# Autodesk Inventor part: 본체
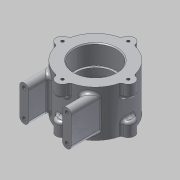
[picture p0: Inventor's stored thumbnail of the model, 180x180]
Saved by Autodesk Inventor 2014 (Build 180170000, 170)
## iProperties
Created: 2015-03
Part Number: 본체
Material: 알루미늄 6061
Document SubType Name: Modeling
Designer: MYHOME
Mass: 450.776 g
Surface Area: 332.745 cm^2
Volume: 166.338 cm^3
Density: 2.71 g/cm^3
Appearance: 알루미늄 - 평지
Author: MYHOME
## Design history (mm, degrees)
sketch "스케치1"
  geometry: C1 r 37 at (0, 0); 1 further point
  constraints: 1 centre point, 1 coincident
  dimensions: "d0" = 74 diameter of C1
extrude "돌출1" new body sketch "스케치1" distance "d1" = 52; taper "d2" = 0 deg
sketch "스케치2"
  geometry: C1 r 7 at (0, 37); C2 r 7 at (-37, 0); C3 r 7 at (0, -37); C4 r 7 at (37, 0); A1 r 37 centre (0, 0) between (0, 37) and (-37, 0) reference
  constraints: 4 centre point, 4 point on circle, 2 horizontal alignment, 2 vertical alignment
  dimensions: "d3" = 14 diameter of C1; "d4" = 14 diameter of C2; "d5" = 14 diameter of C3; "d6" = 14 diameter of C4
extrude "돌출2" join sketch "스케치2" distance "d7" = 15; taper "d8" = 0 deg
sketch "스케치3"
  geometry: A1 r 7 centre (0, 37) between (6.969, 36.338) and (-6.969, 36.338) reference; A2 r 7 centre (-37, 0) between (-36.338, 6.969) and (-36.338, -6.969) reference; A3 r 7 centre (0, -37) between (-6.969, -36.338) and (6.969, -36.338) reference; A4 r 7 centre (37, 0) between (36.338, -6.969) and (36.338, 6.969) reference; 4 further points
  constraints: 4 coincident
hole "구멍1" sketch "스케치3" at (-37, 0), (0, -37), (37, 0), (0, 37) diameter "d9" = 3.242; stored, may be unused: countersink angle "d13" = 90 deg, drill point angle "d15" = 118 deg; dims "d10" = 8, "d11" = 4, "d12" = 2, "d14" = 11
node "작업 평면1"
hole "구멍2" diameter "d19" = 47; stored, may be unused: countersink angle "d23" = 90 deg, drill point angle "d25" = 0 deg; dims "d17" = 10, "d18" = 10, "d20" = 8, "d21" = 4, "d22" = 2, "d24" = 22
hole "구멍3" diameter "d28" = 42; stored, may be unused: countersink angle "d32" = 90 deg, drill point angle "d34" = 0 deg; dims "d26" = 10, "d27" = 10, "d29" = 8, "d30" = 47, "d31" = 22, "d33" = 30
sketch "스케치4"
  geometry: L1 (29, -22.978)-(29, -56); L2 (29, -56)-(19, -56); L3 (19, -56)-(19, -31.749); A1 r 37 centre (0, 0) between (-36.338, -6.969) and (-6.969, -36.338) reference; A2 r 37 centre (0, 0) between (6.969, -36.338) and (36.338, -6.969) reference; 1 further point
  constraints: 6 end point, 2 point on circle, 1 parallel, 1 perpendicular, 1 vertical
  dimensions: "d35" = 10 distance of L1.end L2.end; "d36" = 56 vertical distance of point (0, 0) L1.end; "d37" = 29 horizontal distance of L1.end point (0, 0)
extrude "돌출3" join sketch "스케치4" stored distance "d38" = 40; taper "d39" = 0 deg
fillet "모깎기1" dims "d40" = 5
chamfer "모따기1" distance "d41" = 1; stored, may be unused: second distance "d42" = 2, angle "d43" = 45 deg
fillet "모깎기2" dims "d44" = 0.3
sketch "스케치5"
  geometry: L1 (-43, 0)-(-43, 30) reference; L2 (-53, 0)-(-53, 30) reference; A1 r 5 centre (0, 0) between (-5, 0) and (5, 0) reference; A2 r 5 centre (0, 30) between (5, 30) and (-5, 30) reference; A3 r 5 centre (-48, 0) between (-53, 0) and (-43, 0) reference; A4 r 5 centre (-48, 30) between (-43, 30) and (-53, 30) reference; 5 further points
  constraints: 4 coincident
hole "구멍4" sketch "스케치5" at (-48, 30), (-48, 0), (0, 0), (0, 30) diameter "d45" = 4.134; stored, may be unused: countersink angle "d49" = 90 deg, drill point angle "d51" = 118 deg; dims "d46" = 6, "d47" = 47, "d48" = 22, "d50" = 8
sketch "스케치6"
  geometry: L1 (0, 0)-(-37, 0); L2 (0, 0)-(-26.163, 26.163); A1 r 37 centre (0, 0) between (-6.969, 36.338) and (-36.338, 6.969) reference; A2 r 7 centre (-37, 0) between (-36.338, 6.969) and (-36.338, -6.969) reference; 1 further point
  constraints: 4 end point, 1 horizontal, 1 point on circle
node "작업 평면2"
sketch "스케치7"
  geometry: L1 (-20.767, -26)-(20.767, -26) reference; 3 further points
  constraints: 1 coincident, 1 other
  dimensions: "d58" = 26 distance from line of L1 point (0, 0)
feature "엠보싱1" sketch "스케치7" dims "d52" = 0.5, "d53" = 0
fillet "모깎기3" dims "d54" = 3
fillet "모깎기4" dims "d55" = 3
fillet "모깎기5" dims "d56" = 3
node "솔리드1"
mirror "대칭1"
mirror "대칭2"
node "투영된 루프1"
other parameters: "d16" = 26
